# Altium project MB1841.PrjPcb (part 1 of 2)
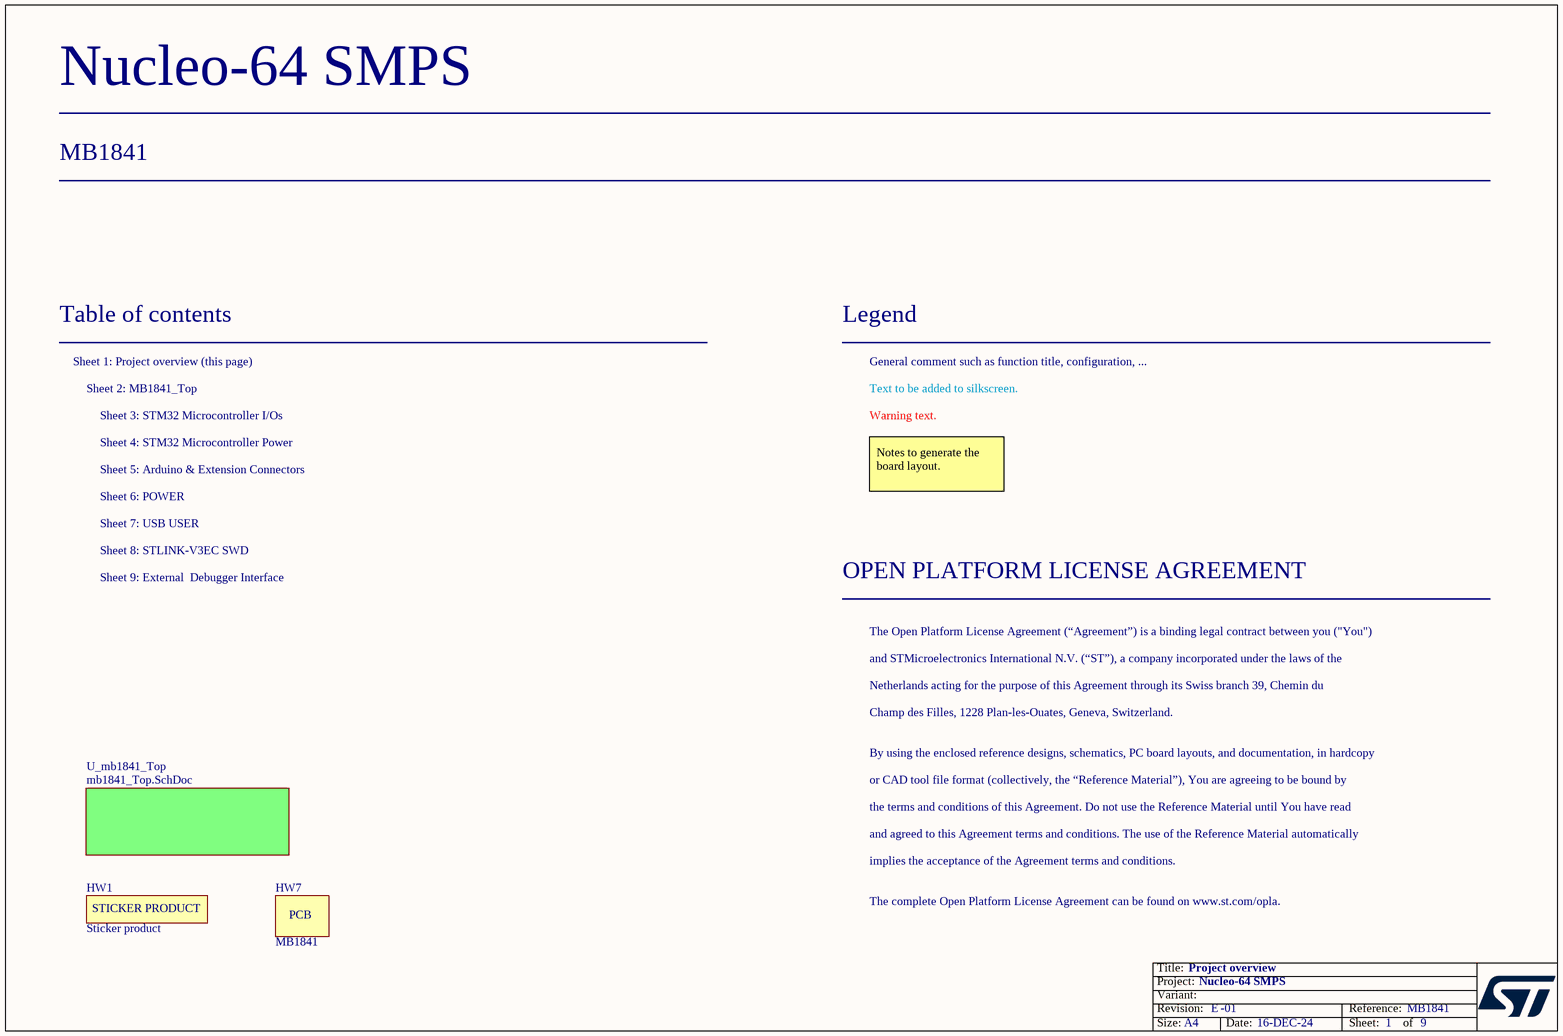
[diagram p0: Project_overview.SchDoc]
Board_Reference: MB1841; Board_PCB_Revision: E; Board_Name: Nucleo-64 SMPS; Board_Document_Date: 16-DEC-24; Board_Assembly_Revision: 01
9 sheets, 261 parts. Net scope: flat (ports and power ports of the same name join across sheets).
Board file: MB1841.PcbDoc
Sheets:
  Project_overview.SchDoc
    U_mb1841_Top = mb1841_Top.SchDoc
      U_Arduino_extension_connectors = Arduino_extension_connectors.SchDoc
      U_Power = Power.SchDoc
      U_STM32_microcontroller_IOs = STM32_microcontroller_IOs.SchDoc
      U_STM32_microcontroller_power = STM32_microcontroller_power.SchDoc
      U_USB = USB.SchDoc
      U_STLink_V3EC = STLink_V3EC.SchDoc
      U_External_Debug_Interface = External_Debug_Interface.SchDoc

## Sheet Project_overview.SchDoc: Project overview
size A4; Date: Not used; ApprovedBy: Not used; CheckedBy: Not used; Author: Not used; CompanyName: STMicroelectronics; DrawnBy: Not used; Engineer: Not used; Organization: Not used; Address1: Not used; Address2: Not used; Address3: Not used; Address4: Not used; DocumentNumber: 1; Revision: Not used; SheetNumber: 1; SheetTotal: 9

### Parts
HW1  value Sticker product  [STICKER_PRODUCT_25X9]  (hidden comment: STICKER_PRODUCT)  (no BOM)
HW7  value MB1841  (hidden comment: PCB)  (no BOM)

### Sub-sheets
U_mb1841_Top = mb1841_Top.SchDoc: no entries

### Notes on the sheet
- Table of contents
- Sheet 1: Project overview (this page)
- Legend
- General comment such as function title, configuration, ...
- Sheet 2: MB1841_Top
- Sheet 4: STM32 Microcontroller Power
- Sheet 3: STM32 Microcontroller I/Os
- Text to be added to silkscreen.
- Warning text.
- Sheet 6: POWER
- Sheet 5: Arduino & Extension Connectors
- Notes to generate the board layout.
- Sheet 8: STLINK-V3EC SWD
- Sheet 7: USB USER
- Sheet 9: External  Debugger Interface
- OPEN PLATFORM LICENSE AGREEMENT
- The Open Platform License Agreement (“Agreement”) is a binding legal contract between you ("You")
- and STMicroelectronics International N.V. (“ST”), a company incorporated under the laws of the
- Netherlands acting for the purpose of this Agreement through its Swiss branch 39, Chemin du
- Champ des Filles, 1228 Plan-les-Ouates, Geneva, Switzerland.
- By using the enclosed reference designs, schematics, PC board layouts, and documentation, in hardcopy
- or CAD tool file format (collectively, the “Reference Material”), You are agreeing to be bound by
- the terms and conditions of this Agreement. Do not use the Reference Material until You have read
- and agreed to this Agreement terms and conditions. The use of the Reference Material automatically
- implies the acceptance of the Agreement terms and conditions.
- The complete Open Platform License Agreement can be found on www.st.com/opla.

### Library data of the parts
HW1 = MCD-00547: Sticker product 25x9 mm; Part_Type: Misc; Part_Preference: Recommended; Component_Country_Of_Origin: Unknown; ShowFields: YES; ID: 3197
HW7 = MCD-04244: MB1841 PCB Nucleo 4L2S; Part_Preference: Recommended; ShowFields: YES; ID: 6360

## Sheet mb1841_Top.SchDoc: Top hierarchical view
size A4; Date: Not used; ApprovedBy: Not used; CheckedBy: Not used; Author: Not used; CompanyName: STMicroelectronics; DrawnBy: Not used; Engineer: Not used; Organization: Not used; Address1: Not used; Address2: Not used; Address3: Not used; Address4: Not used; DocumentNumber: 2; Revision: A-01-P3; SheetNumber: 2; SheetTotal: 9
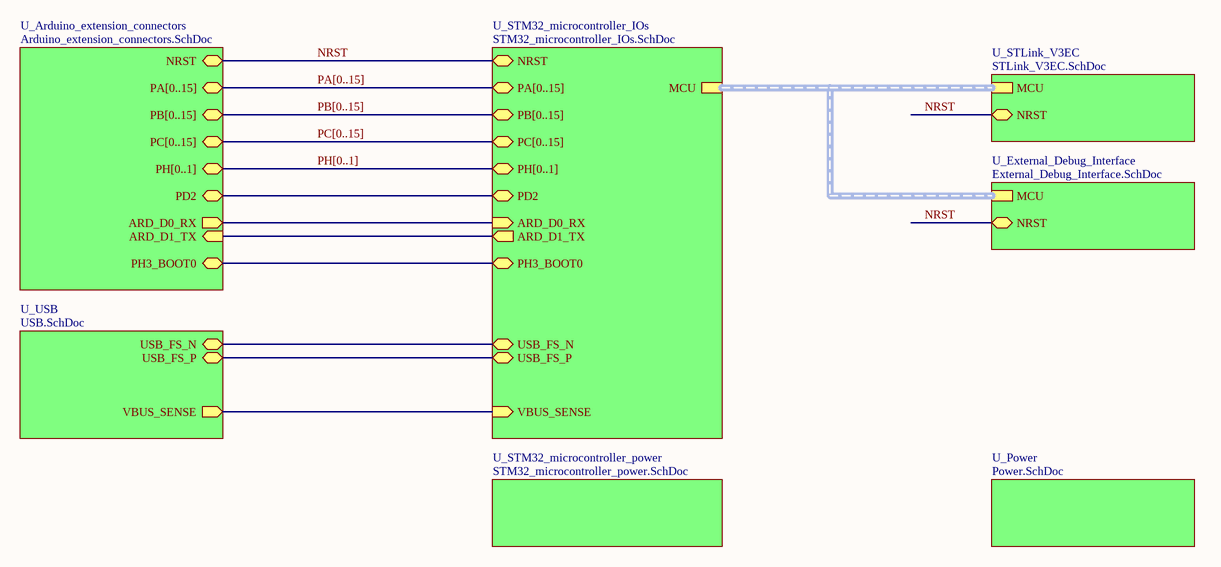
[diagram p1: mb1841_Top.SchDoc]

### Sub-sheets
U_Arduino_extension_connectors = Arduino_extension_connectors.SchDoc: PA[0..15] (bidir), PB[0..15] (bidir), PC[0..15] (bidir), PH[0..1] (bidir), PH3_BOOT0 (bidir), PD2 (bidir), ARD_D0_RX (out), ARD_D1_TX (in), NRST (bidir)
U_External_Debug_Interface = External_Debug_Interface.SchDoc: NRST (bidir), MCU (harness MCU)
U_Power = Power.SchDoc: no entries
U_STLink_V3EC = STLink_V3EC.SchDoc: NRST (bidir), MCU (harness MCU)
U_STM32_microcontroller_IOs = STM32_microcontroller_IOs.SchDoc: PA[0..15] (bidir), PB[0..15] (bidir), PC[0..15] (bidir), PH[0..1] (bidir), PH3_BOOT0 (bidir), ARD_D0_RX (in), PD2 (bidir), ARD_D1_TX (out), USB_FS_P (bidir), USB_FS_N (bidir), VBUS_SENSE (in), MCU (harness MCU), NRST (bidir)
U_STM32_microcontroller_power = STM32_microcontroller_power.SchDoc: no entries
U_USB = USB.SchDoc: USB_FS_N (bidir), USB_FS_P (bidir), VBUS_SENSE (out)

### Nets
NRST: sheet U_Arduino_extension_connectors/NRST, sheet U_STM32_microcontroller_IOs/NRST, sheet U_STLink_V3EC/NRST, sheet U_External_Debug_Interface/NRST
(unnamed): sheet U_Arduino_extension_connectors/PH3_BOOT0, sheet U_STM32_microcontroller_IOs/PH3_BOOT0
(unnamed): sheet U_Arduino_extension_connectors/PD2, sheet U_STM32_microcontroller_IOs/PD2  [a separate net that carries the same name]
(unnamed): sheet U_Arduino_extension_connectors/ARD_D0_RX, sheet U_STM32_microcontroller_IOs/ARD_D0_RX  [a separate net that carries the same name]
(unnamed): sheet U_Arduino_extension_connectors/ARD_D1_TX, sheet U_STM32_microcontroller_IOs/ARD_D1_TX  [a separate net that carries the same name]
(unnamed): sheet U_STM32_microcontroller_IOs/USB_FS_P, sheet U_USB/USB_FS_P  [a separate net that carries the same name]
(unnamed): sheet U_STM32_microcontroller_IOs/USB_FS_N, sheet U_USB/USB_FS_N  [a separate net that carries the same name]
(unnamed): sheet U_STM32_microcontroller_IOs/VBUS_SENSE, sheet U_USB/VBUS_SENSE  [a separate net that carries the same name]

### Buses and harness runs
bus PA[0..15] = sheet U_Arduino_extension_connectors/PA[0..15] = sheet U_STM32_microcontroller_IOs/PA[0..15]
bus PB[0..15] = sheet U_Arduino_extension_connectors/PB[0..15] = sheet U_STM32_microcontroller_IOs/PB[0..15]
bus PC[0..15] = sheet U_Arduino_extension_connectors/PC[0..15] = sheet U_STM32_microcontroller_IOs/PC[0..15]
bus PH[0..1] = sheet U_Arduino_extension_connectors/PH[0..1] = sheet U_STM32_microcontroller_IOs/PH[0..1]
harness sheet U_External_Debug_Interface/MCU = sheet U_STLink_V3EC/MCU = sheet U_STM32_microcontroller_IOs/MCU

## Sheet Arduino_extension_connectors.SchDoc: Arduino & Extension Connectors
size A4; Date: Not used; ApprovedBy: Not used; CheckedBy: Not used; Author: Not used; CompanyName: STMicroelectronics; DrawnBy: Not used; Engineer: Not used; Organization: Not used; Address1: Not used; Address2: Not used; Address3: Not used; Address4: Not used; DocumentNumber: 5; Revision: Not used; SheetNumber: 5; SheetTotal: 9
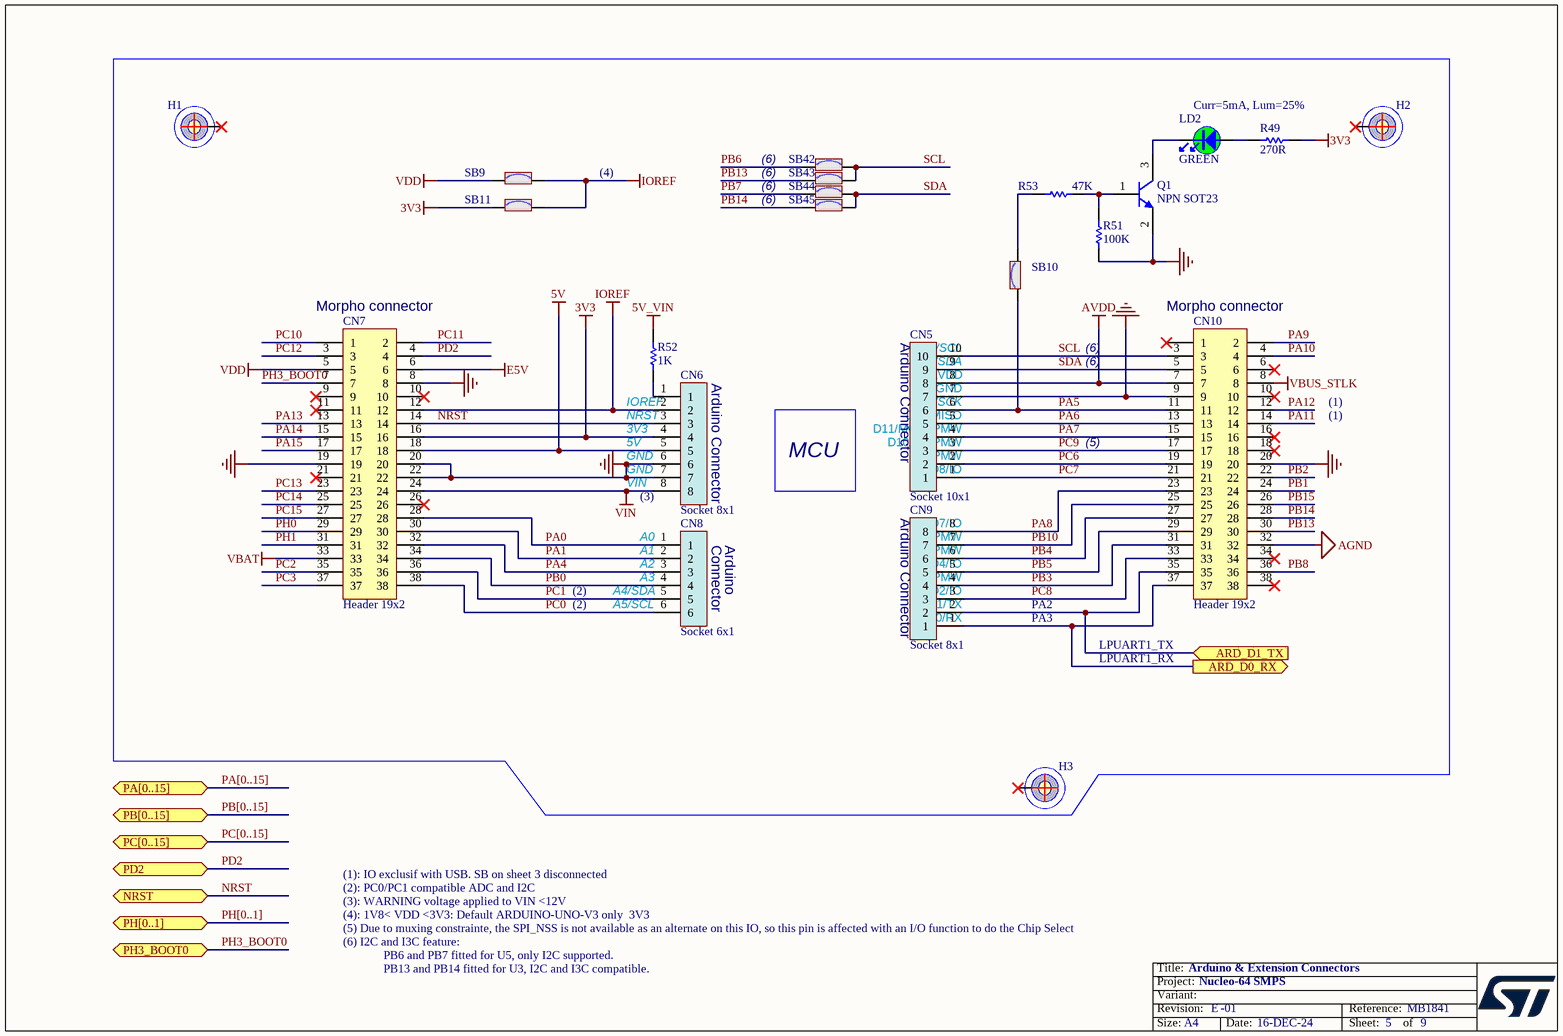
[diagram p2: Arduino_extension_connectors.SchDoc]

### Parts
CN5  Socket 10x1  [CON_SAMTEC_SSQ-110-03-F-S]
CN6  Socket 8x1  [CON_SAMTEC_SSQ-108-03-F-S]
CN7  Header 19x2  [CON_SAMTEC_TSW-119-09-X-D]
CN8  Socket 6x1  [CON_SAMTEC_SSQ-106-03-F-S]
CN9  Socket 8x1  [CON_SAMTEC_SSQ-108-03-F-S]
CN10  Header 19x2  [CON_SAMTEC_TSW-119-09-X-D]
H1  POSITION HOLE  (value not drawn)  (no BOM)
H2  POSITION HOLE  (value not drawn)  (no BOM)
H3  POSITION HOLE  (value not drawn)  (no BOM)
LD2  value GREEN  [LED_0603_OSRAM_LG-Q396-PS-35_GREEN_1A2K_H0P4]  (hidden comment: LED_green)
Q1  value NPN SOT23  [NPN_SOT23]  (hidden comment: 9013-SOT23)
R49  value 270R  [R0402]  (hidden comment: Resistor)
R51  value 100K  [R0402]  (hidden comment: Resistor)
R52  value 1K  [R0402]  (hidden comment: Resistor)
R53  value 47K  [R0402]  (hidden comment: Resistor)
SB9  SB_ON  [SOLDER-BRIDGE_R0603-0R]  (value not drawn)
SB10  SB_ON  [SOLDER-BRIDGE_R0603-0R]  (value not drawn)
SB11  SB_ON  [SOLDER-BRIDGE_R0603-0R]  (value not drawn)
SB42  SB_ON  [SOLDER-BRIDGE_R0603-0R]  (value not drawn)
SB43  SB_ON  [SOLDER-BRIDGE_R0603-0R]  (value not drawn)
SB44  SB_ON  [SOLDER-BRIDGE_R0603-0R]  (value not drawn)
SB45  SB_ON  [SOLDER-BRIDGE_R0603-0R]  (value not drawn)

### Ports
ARD_D0_RX (out), ARD_D1_TX (in), NRST (bidir), PA[0..15] (bidir), PB[0..15] (bidir), PC[0..15] (bidir), PD2 (bidir), PH3_BOOT0 (bidir), PH[0..1] (bidir)

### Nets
3V3: CN6.4 CN7.16 R49.2 SB11.1
5V: CN6.5 CN7.18
5V_VIN: R52.1
AGND: CN10.32
AVDD: CN5.8 CN10.7
E5V: CN7.6
GND: CN5.7 CN6.6 CN6.7 CN7.8 CN7.19 CN7.20 CN7.22 CN10.9 CN10.20 Q1.2(E) R51.1
IOREF: CN6.2 CN7.12 SB9.2 SB11.2
VBAT: CN7.33
VBUS_STLK: CN10.8
VDD: CN7.5 SB9.1
VIN: CN6.8 CN7.24
ARD_D0_RX: CN9.1 CN10.37 ; port ARD_D0_RX
ARD_D1_TX: CN9.2 CN10.35 ; port ARD_D1_TX
NRST: CN6.3 CN7.14 ; port NRST
PA0: CN7.28 CN8.1
PA1: CN7.30 CN8.2
PA4: CN7.32 CN8.3
PA5: CN5.6 CN10.11 SB10.1
PA6: CN5.5 CN10.13
PA7: CN5.4 CN10.15
PA8: CN9.8 CN10.23
PA9: CN10.2
PA10: CN10.4
PA11: CN10.14
PA12: CN10.12
PA13: CN7.13
PA14: CN7.15
PA15: CN7.17
PB0: CN7.34 CN8.4
PB1: CN10.24
PB2: CN10.22
PB3: CN9.4 CN10.31
PB4: CN9.6 CN10.27
PB5: CN9.5 CN10.29
PB6: SB42.1
PB7: SB44.1
PB8: CN10.36
PB10: CN9.7 CN10.25
PB13: CN10.30 SB43.1
PB14: CN10.28 SB45.1
PB15: CN10.26
PC0: CN7.38 CN8.6
PC1: CN7.36 CN8.5
PC2: CN7.35
PC3: CN7.37
PC6: CN5.2 CN10.19
PC7: CN5.1 CN10.21
PC8: CN9.3 CN10.33
PC9: CN5.3 CN10.17
PC10: CN7.1
PC11: CN7.2
PC12: CN7.3
PC13: CN7.23
PC14: CN7.25
PC15: CN7.27
PD2: CN7.4 ; port PD2
PH0: CN7.29
PH1: CN7.31
PH3_BOOT0: CN7.7 ; port PH3_BOOT0
SCL: CN5.10 CN10.3 SB42.2 SB43.2
SDA: CN5.9 CN10.5 SB44.2 SB45.2
NetCN6_1: CN6.1 R52.2
NetLD2_1: LD2.1 R49.1
NetLD2_2: LD2.2 Q1.3(C)
NetQ1_1: Q1.1(B) R51.2 R53.2
NetR53_1: R53.1 SB10.2

Not connected (* = marked no-connect by the designer): CN7 9* 10* 11* 21* 26*; CN10 1* 6* 10* 16* 18* 34* 38*; H1 1*; H2 1*; H3 1*

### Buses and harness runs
bus PA[0..15] = port PA[0..15]
bus PB[0..15] = port PB[0..15]
bus PC[0..15] = port PC[0..15]
bus PH[0..1] = port PH[0..1]

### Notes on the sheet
- Curr=5mA, Lum=25%
- (4)
- (6)
- (near CN7) Morpho connector
- (near CN10) Morpho connector
- (near CN6) Arduino Connector
- (near CN5) Arduino Connector
- (near CN5) D14/SDA
- (near CN5) D15/SCL
- (near CN5) AVDD
- (near CN6) 5V
- 3V3
- NRST
- IOREF
- (near CN5) D10/CS/PMW
- (near CN5) D13/SCK
- (near CN5) D12/MISO
- (near CN5) D11/MOSI/PMW
- (near CN5) GND
- (5)
- (1)
- (near CN6) VIN
- (near CN6) GND
- (near CN6) (3)
- MCU
- (near CN9) Arduino Connector
- (near CN5) D8/IO
- (near CN5) D9/PMW
- (near CN8) A0
- (near CN8) A1
- (near CN8) A2
- (near CN8) A3
- (near CN8) Connector
- (near CN8) Arduino
- (near CN9) D4/IO
- (near CN9) D3/PMW
- (near CN9) D5/PMW
- (near CN9) D6/PMW
- (near CN9) D7/IO
- (2)
- (near CN8) A4/SDA
- (near CN8) A5/SCL
- (near CN9) D0/RX
- (near CN9) D1/TX
- (near CN9) D2/IO
- PA2
- PA3
- LPUART1_TX
- LPUART1_RX
- (2): PC0/PC1 compatible ADC and I2C
- (1): IO exclusif with USB. SB on sheet 3 disconnected
- (4): 1V8< VDD <3V3: Default ARDUINO-UNO-V3 only  3V3
- (3): WARNING voltage applied to VIN <12V
- (5) Due to muxing constrainte, the SPI_NSS is not available as an alternate on this IO, so this pin is affected with an I/O function to do the Chip Select
- (6) I2C and I3C feature:
- PB6 and PB7 fitted for U5, only I2C supported.
- PB13 and PB14 fitted for U3, I2C and I3C compatible.

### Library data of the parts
CN5 = MCD-02625: Socket, 10x1, 2.54mm, VR, TH, T=8.51mm/10mm; Part_Type: Connector; Part_Preference: Recommended; Manufacturer: SAMTEC; Manufacturer_Part_Number: SSQ-110-03-F-S; Order_Code_RS: 154-8308; Component_Country_Of_Origin: China, Costa Rica,  Malaysia, Vietnam, USA; ShowFields: YES; ID: 4731
CN6 CN9 = MCD-02624: Socket, 8x1, 2.54mm, VR, TH, T=8.51mm/10mm; Part_Type: Connector; Part_Preference: Recommended; Manufacturer: SAMTEC; Manufacturer_Part_Number: SSQ-108-03-F-S; Order_Code_RS: 180-0395; Component_Country_Of_Origin: China, Costa Rica,  Malaysia, Vietnam, USA; ShowFields: YES; ID: 4730
CN7 CN10 = MCD-00213: Header, 19x2, 2.54mm, VR, TH, T=5.84mm/10.16mm; Manufacturer_Part_Number: TSW-119-09-G-D; Manufacturer: SAMTEC; Part_Type: Connector; Part_Preference: Recommended; Component_Country_Of_Origin: China, Costa Rica, Malaysia, United States, Vietnam; ShowFields: YES; ID: 2656
CN8 = MCD-02623: Socket, 6x1, 2.54mm, VR, TH, T=8.51mm/10mm; Part_Type: Connector; Part_Preference: Recommended; Manufacturer: SAMTEC; Manufacturer_Part_Number: SSQ-106-03-F-S; Order_Code_RS: 180-0379; Component_Country_Of_Origin: China, Costa Rica,  Malaysia, Vietnam, USA; ShowFields: YES; ID: 4729
H1-H3 = MCD-03341: POSITION HOLE D3R2 COMPLIANT ARDUINO; Part_Type: Misc; Part_Preference: Recommended; Value: PTH 3.2mm; ShowFields: YES; ID: 5457
LD2 = MCD-00588: LED Green, 0603 SMD, Forward Voltage Typ=2V, Max=2.5V; Part_Type: Display; Manufacturer_Part_Number: LG Q396-PS-35; Manufacturer: OSRAM OPTO SEMICONDUCTORS; Part_Preference: Recommended; Full_Alternate_Internal_Part_Number: MCD-02400; Component_Country_Of_Origin: Unknown; ShowFields: YES; ID: 3155
Q1 = MCD-00073: NPN Bipolar Transistor; Part_Type: IC; Manufacturer_Part_Number: BSR14; Manufacturer: ON SEMICONDUCTOR; Part_Preference: Recommended; Component_Country_Of_Origin: Unknown; ShowFields: YES; ID: 2519
R49 = MCD-00441: Resistor, 270R, 0402, +/-1%, 1/16W; Manufacturer_Part_Number: RC0402FR-07270RL; Manufacturer: YAGEO; Part_Preference: Recommended; Component_Country_Of_Origin: China; ShowFields: YES; ID: 2838
R51 = MCD-00059: Resistor, 100K, 0402, +/-1%, 1/16W; Part_Preference: Recommended; Manufacturer: YAGEO; Manufacturer_Part_Number: RC0402FR-07100KL; Component_Country_Of_Origin: China; ShowFields: YES; ID: 2533
R52 = MCD-00061: Resistor, 1K, 0402, +/-1%,1/16W; Part_Preference: Recommended; Manufacturer: YAGEO; Manufacturer_Part_Number: RC0402FR-071KL; Component_Country_Of_Origin: China; ShowFields: YES; ID: 2532
R53 = MCD-00063: Resistor, 47K, 0402, +/-1%, 1/16W; Manufacturer_Part_Number: RC0402FR-0747KL; Manufacturer: YAGEO; Part_Preference: Recommended; Component_Country_Of_Origin: China; ShowFields: YES; ID: 2528
SB9-SB11 SB42-SB45 = MCD-00071: Solder Bridge ON; Part_Type: Misc; Manufacturer_Part_Number: RC0603JR-070RL; Manufacturer: YAGEO; Part_Preference: Recommended; ShowFields: YES; ID: 2521

## Sheet Power.SchDoc: Power
size A4; Date: Not used; ApprovedBy: Not used; CheckedBy: Not used; Author: Not used; CompanyName: STMicroelectronics; DrawnBy: Not used; Engineer: Not used; Organization: Not used; Address1: Not used; Address2: Not used; Address3: Not used; Address4: Not used; DocumentNumber: 6; Revision: Not used; SheetNumber: 6; SheetTotal: 9
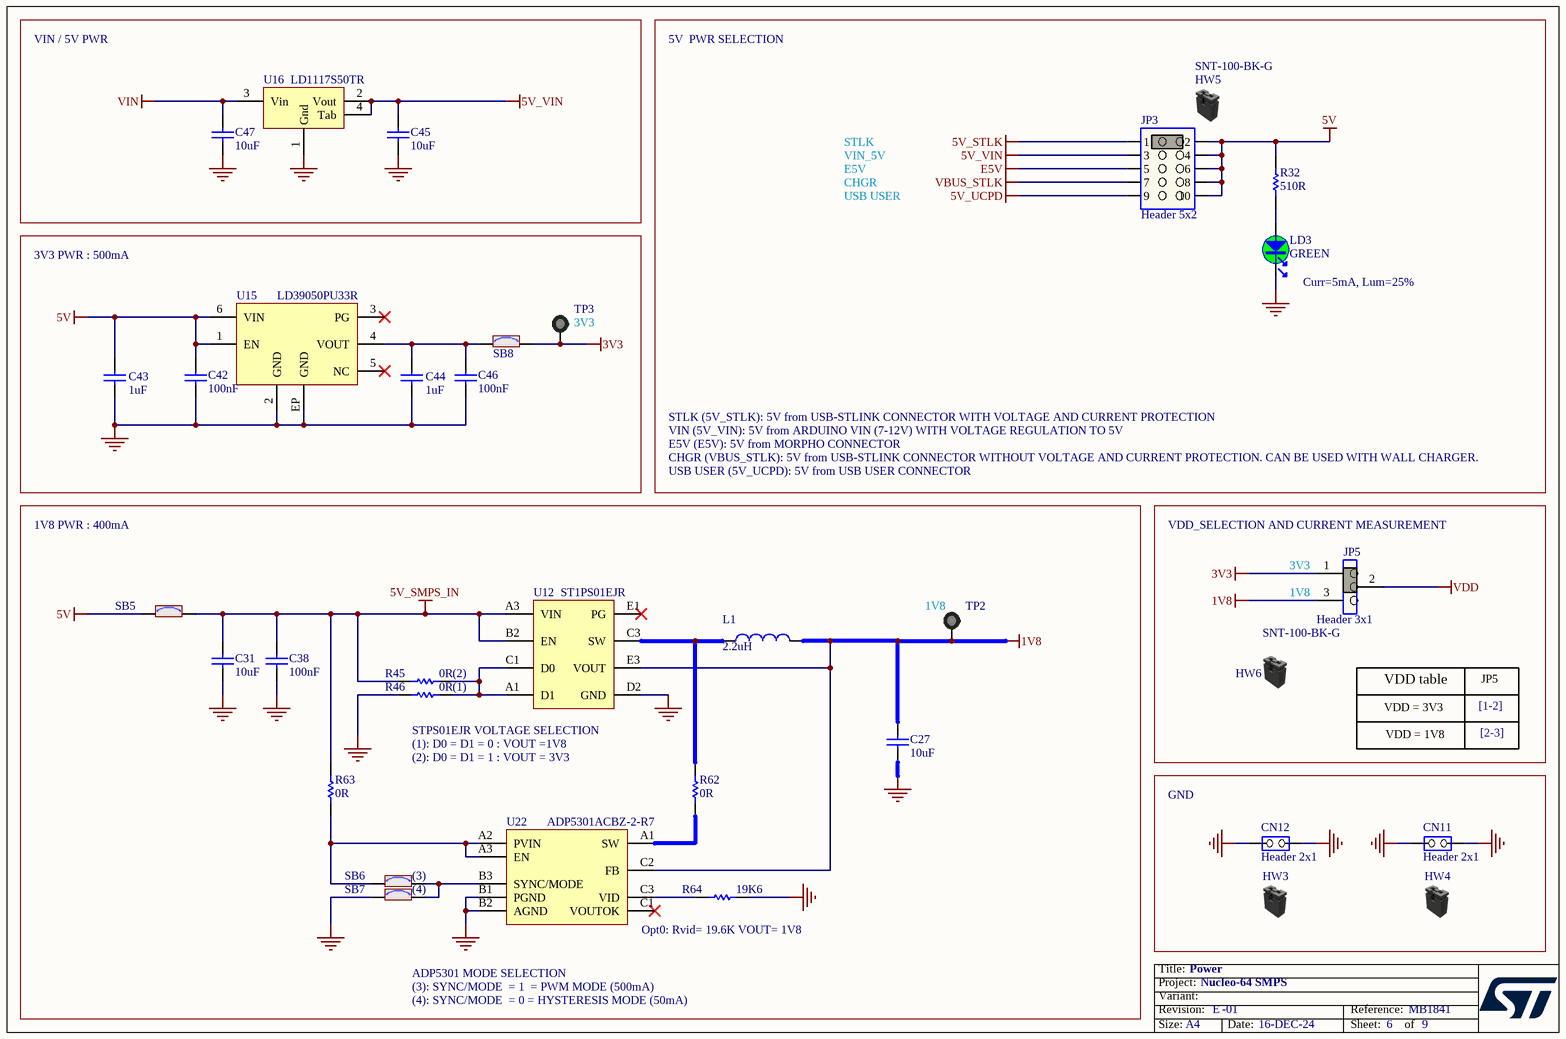
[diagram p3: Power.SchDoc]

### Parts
C27  value 10uF  [C0603]  (hidden comment: Capacitor)
C31  value 10uF  [C0603]  (hidden comment: Capacitor)
C38  value 100nF  [C0402]  (hidden comment: Capacitor)
C42  value 100nF  [C0402]  (hidden comment: Capacitor)
C43  value 1uF  [C0603]  (hidden comment: Capacitor)
C44  value 1uF  [C0603]  (hidden comment: Capacitor)
C45  value 10uF  [C0805]  (hidden comment: Capacitor)
C46  value 100nF  [C0402]  (hidden comment: Capacitor)
C47  value 10uF  [C0805]  (hidden comment: Capacitor)
CN11  value Header 2x1  [CON_SAMTEC_TSW-102-09-X-S]  (hidden comment: Jumper_Header 2x1)
CN12  value Header 2x1  [CON_SAMTEC_TSW-102-09-X-S]  (hidden comment: Jumper_Header 2x1)
HW3  Shunt Black 2.54mm  (value not drawn)  (mechanical)
HW4  Shunt Black 2.54mm  (value not drawn)  (mechanical)
HW5  value SNT-100-BK-G  (hidden comment: Shunt Black 2.54mm)  (mechanical)
HW6  value SNT-100-BK-G  (hidden comment: Shunt Black 2.54mm)  (mechanical)
JP3  value Header 5x2  [CON_SAMTEC_TSW-105-07-X-D]  (hidden comment: Jumper_Header 5x2 Fitted 1-2)
JP5  value Header 3x1  [CON_SAMTEC_TSW-103-07-F-S]  (hidden comment: Jumper_Header 3x1 Fitted 1-2)
L1  value 2.2uH  [IND_TDK_VLS252010HBX-1]  (hidden comment: Inductor)
LD3  value GREEN  [LED_0603_OSRAM_LG-Q396-PS-35_GREEN_1A2K_H0P4]  (hidden comment: LED_green)
R32  value 510R  [R0603]  (hidden comment: Resistor)
R45  value 0R  [R0603]  (hidden comment: Resistor)
R46  value 0R  [R0603]  (hidden comment: Resistor)
R62  value 0R  [R0603]  (hidden comment: Resistor)
R63  value 0R  [R0603]  (hidden comment: Resistor)
R64  value 19K6  [R0603]  (hidden comment: Resistor)
SB5  SB_ON  [SOLDER-BRIDGE_R0603-0R]  (value not drawn)
SB6  SB_ON  [SOLDER-BRIDGE_R0603-0R]  (value not drawn)
SB7  SB_ON  [SOLDER-BRIDGE_R0603-0R]  (value not drawn)
SB8  SB_ON  [SOLDER-BRIDGE_R0603-0R]  (value not drawn)
TP2  Test_Point_PTH_1mm_2mm  [TP_PTH_1MM_2MM]  (value not drawn)  (no BOM)
TP3  Test_Point_PTH_1mm_2mm  [TP_PTH_1MM_2MM]  (value not drawn)  (no BOM)
U12  ST1PS01EJR  [ICC_FLIP-CHIP-BGA8_1P11X1P41_P040]
U15  LD39050PU33R  [ICC_DFN6-EPAD_3X3_P095]
U16  LD1117S50TR  [REG_SOT223-TAB]
U22  value ADP5301ACBZ-2-R7  [ICC_WLCSP9_1P65X1P87_P050]  (hidden comment: ADP5301)

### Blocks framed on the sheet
VIN / 5V PWR: C45 C47 U16
VDD table: HW6 JP5
GND: CN11 CN12 HW3 HW4

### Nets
1V8: C27.2 JP5.3 L1.2 TP2.1 U12.E3(VOUT) U22.C2(FB)
3V3: JP5.1 SB8.2 TP3.1
5V: C42.2 C43.2 JP3.2 JP3.4 JP3.6 JP3.8 JP3.10 R32.2 SB5.1 U15.1(EN) U15.6(VIN)
5V_SMPS_IN: C31.2 C38.2 R45.2 R63.1 SB5.2 U12.A3(VIN) U12.B2(EN)
5V_STLK: JP3.1
5V_UCPD: JP3.9
5V_VIN: C45.2 JP3.3 U16.2(Vout) U16.4(Tab)
E5V: JP3.5
GND: C27.1 C31.1 C38.1 C42.1 C43.1 C44.1 C45.1 C46.1 C47.1 CN11.1(COMMON) CN11.2(NO) CN12.1(COMMON) CN12.2(NO) LD3.2 R46.2 R64.2 SB7.1 U12.D2(GND) U15.2(GND) U15.EP(GND) U16.1(Gnd) U22.B1(PGND) U22.B2(AGND)
VBUS_STLK: JP3.7
VDD: JP5.2
VIN: C47.2 U16.3(Vin)
NetC44_2: C44.2 C46.2 SB8.1 U15.4(VOUT)
NetL1_1: L1.1 R62.1 U12.C3(SW)
NetLD3_1: LD3.1 R32.1
NetR45_1: R45.1 R46.1 U12.A1(D1) U12.C1(D0)
NetR62_2: R62.2 U22.A1(SW)
NetR63_2: R63.2 SB6.1 U22.A2(PVIN) U22.A3(EN)
NetR64_1: R64.1 U22.C3(VID)
NetSB6_2: SB6.2 SB7.2 U22.B3(SYNC/MODE)

Not connected (* = marked no-connect by the designer): U12 E1(PG)*; U15 3(PG)* 5(NC)*; U22 C1(VOUTOK)*

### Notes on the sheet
- 5V  PWR SELECTION
- STLK
- E5V
- VIN_5V
- CHGR
- USB USER
- 3V3 PWR : 500mA
- (near LD3) Curr=5mA, Lum=25%
- (near TP3) 3V3
- STLK (5V_STLK): 5V from USB-STLINK CONNECTOR WITH VOLTAGE AND CURRENT PROTECTION
- VIN (5V_VIN): 5V from ARDUINO VIN (7-12V) WITH VOLTAGE REGULATION TO 5V
- E5V (E5V): 5V from MORPHO CONNECTOR
- CHGR (VBUS_STLK): 5V from USB-STLINK CONNECTOR WITHOUT VOLTAGE AND CURRENT PROTECTION. CAN BE USED WITH WALL CHARGER.
- USB USER (5V_UCPD): 5V from USB USER CONNECTOR
- 1V8 PWR : 400mA
- (near JP5) VDD_SELECTION AND CURRENT MEASUREMENT
- (near JP5) 3V3
- (near TP2) 1V8
- (near JP5) 1V8
- (1)
- (2)
- VDD = 3V3
- [1-2]
- JP5
- STPS01EJR VOLTAGE SELECTION
  (1): D0 = D1 = 0 : VOUT =1V8
  (2): D0 = D1 = 1 : VOUT = 3V3
- VDD = 1V8
- [2-3]
- (near SB6) (3)
- (4)
- Opt0: Rvid= 19.6K VOUT= 1V8
- ADP5301 MODE SELECTION
  (3): SYNC/MODE  = 1  = PWM MODE (500mA)
  (4): SYNC/MODE  = 0 = HYSTERESIS MODE (50mA)

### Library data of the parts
C27 C31 = MCD-00243: Capacitor, MLCC, 10uF, 6V3, X5R, +/-10%, 0603, T=0.8mm; Manufacturer_Part_Number: CC0603KRX5R5BB106; Manufacturer: YAGEO; Part_Preference: Recommended; Component_Country_Of_Origin: China; ShowFields: YES; ID: 2626
C38 = MCD-00006: Capacitor, MLCC, 100nF, 16V, X7R, +/-10%, 0402, T=0.5mm; Manufacturer_Part_Number: CC0402KRX7R7BB104; Manufacturer: YAGEO; Part_Preference: Recommended; Order_Code_RS: 616-9701; Component_Country_Of_Origin: China; ShowFields: YES; ID: 2474
C42 C46 = MCD-00006: Capacitor, MLCC, 100nF, 16V, X7R, +/-10%, 0402, T=0.5mm; Part_Preference: Recommended; Manufacturer: YAGEO; Manufacturer_Part_Number: CC0402KRX7R7BB104; Order_Code_RS: 616-9701; Component_Country_Of_Origin: China; ShowFields: YES; ID: 2474
C43 C44 = MCD-00010: Capacitor, MLCC, 1uF, 16V, X5R, +/-10%, 0603, T=0.8mm; Manufacturer_Part_Number: CC0603KRX5R7BB105; Manufacturer: YAGEO; Part_Preference: Recommended; Component_Country_Of_Origin: China; ShowFields: YES; ID: 2470
C45 C47 = MCD-00014: Capacitor, MLCC, 10uF, 25V, X5R, +/-10%, 0805, T=0.85mm; Manufacturer_Part_Number: CC0805KRX5R8BB106; Manufacturer: YAGEO; Part_Preference: Recommended; Full_Alternate_Internal_Part_Number: MCD-02385; Partial_Alternate_Internal_Part_Number: MCD-03053; Component_Country_Of_Origin: China; ShowFields: YES; ID: 2468
CN11 CN12 = MCD-00214: Header, 2x1, 2.54mm, VR, TH, T=5.84mm/10.16mm; Part_Type: Connector; Part_Preference: Recommended; Manufacturer: SAMTEC; Manufacturer_Part_Number: TSW-102-09-G-S; Full_Alternate_Internal_Part_Number: MCD-02393; Order_Code_RS: 180-3129; Component_Country_Of_Origin: China, Costa Rica, Malaysia, United States, Vietnam; ShowFields: YES; ID: 2652
HW3 HW4 = MCD-00043: SHUNT 2.54mm BLACK; Part_Type: Misc; Part_Preference: Recommended; Manufacturer: SAMTEC; Full_Alternate_Internal_Part_Number: MCD-02388; Value: SNT-100-BK-G; Component_Country_Of_Origin: China, Costa Rica, Malaysia, United States, Vietnam; ShowFields: YES; ID: 2551
HW5 HW6 = MCD-00043: SHUNT 2.54mm BLACK; Manufacturer: SAMTEC; Part_Type: Misc; Part_Preference: Recommended; Full_Alternate_Internal_Part_Number: MCD-02388; Component_Country_Of_Origin: China, Costa Rica, Malaysia, United States, Vietnam; ShowFields: YES; ID: 2551
JP3 = MCD-01203: Header, 5x2, 2.54mm, VR, TH, T=5.84mm/2.54mm; Part_Type: Connector; Manufacturer_Part_Number: TSW-105-07-G-D; Manufacturer: SAMTEC; BMS_Part_Number: 9083523; Part_Preference: Recommended; Full_Alternate_Internal_Part_Number: MCD-02391; Order_Code_RS: 161-2267; Component_Country_Of_Origin: China, Costa Rica, Malaysia, United States, Vietnam; ShowFields: YES; ID: 3293
JP5 = MCD-00684: Header, 3x1, 2.54mm, VR, TH, T=5.84mm/2.54mm; Part_Type: Connector; Manufacturer_Part_Number: TSW-103-07-F-S; Manufacturer: SAMTEC; Part_Preference: Recommended; Order_Code_RS: 161-2248; Component_Country_Of_Origin: China, Costa Rica, Malaysia, United States, Vietnam; ShowFields: YES; ID: 3059
L1 = MCD-00240: Inductor, 2.2uH, +/-20%, 2.6A, 100mR, 2.5x2mm, T=1mm; Manufacturer_Part_Number: VLS252010HBX-2R2M-1; Manufacturer: TDK; Part_Preference: Recommended; Order_Code_RS: 181-5270; Component_Country_Of_Origin: Unknown; ShowFields: YES; ID: 2627
LD3 = MCD-00588: as LD2 on sheet Arduino_extension_connectors
R32 = MCD-00225: Resistor, 510R, 0603, +/-1%, 1/10W; Manufacturer_Part_Number: RC0603FR-07510RL; Manufacturer: YAGEO; Part_Preference: Recommended; Component_Country_Of_Origin: China; ShowFields: YES; ID: 2644
R45 R46 R62 R63 = MCD-00056: Resistor, 0R, 0603, +/-5%, 1/10W; Manufacturer_Part_Number: RC0603JR-070RL; Manufacturer: YAGEO; Part_Preference: Recommended; Component_Country_Of_Origin: China; ShowFields: YES; ID: 2536
R64 = MCD-00242: Resistor, 19K6, 0603, +/-1%, 1/10W; Manufacturer_Part_Number: RC0603FR-0719K6L; Manufacturer: YAGEO; Part_Preference: Recommended; Component_Country_Of_Origin: China; ShowFields: YES; ID: 2630
SB5-SB7 = MCD-00071: Solder Bridge ON; Part_Type: Misc; Part_Preference: Recommended; Manufacturer: YAGEO; Manufacturer_Part_Number: RC0603JR-070RL; ShowFields: YES; ID: 2521
SB8 = MCD-00071: as SB9 on sheet Arduino_extension_connectors
TP2 TP3 = MCD-01506: Test Point trought hole 1mm/2mm; Part_Type: Misc; Part_Preference: Recommended; Value: TP; ShowFields: YES; ID: 3606
U12 = MCD-00228: 400mA Nano-Quiescent Step down converter; Manufacturer: STMICROELECTRONICS; Part_Type: IC; BMS_Part_Number: 9176329; Part_Preference: Recommended; Manufacturer_HQ_COO: EU; Component_Country_Of_Origin: Italy; ShowFields: YES; ID: 2642
U15 = MCD-00215: Low quiescent current and low noise voltage regulators; Manufacturer: STMICROELECTRONICS; Part_Type: IC; BMS_Part_Number: 9176126; Part_Preference: Recommended; Manufacturer_HQ_COO: EU; Component_Country_Of_Origin: Malaysia; ShowFields: YES; ID: 2654
U16 = MCD-00088: IC REG LDO 5V 0.8A SOT223; Manufacturer: STMICROELECTRONICS; BMS_Part_Number: 9176133; Part_Preference: Recommended; Manufacturer_HQ_COO: EU; Component_Country_Of_Origin: China; ShowFields: YES; ID: 2503
U22 = MCD-00226: UL Step down regulator: Opt0; Manufacturer: ANALOG DEVICES; Part_Type: IC; Part_Preference: Recommended; Component_Country_Of_Origin: Singapore; ShowFields: YES; ID: 2641

## Sheet STM32_microcontroller_IOs.SchDoc: STM32 microcontroller I/Os
size A4; Date: Not used; ApprovedBy: Not used; CheckedBy: Not used; Author: Not used; CompanyName: STMicroelectronics; DrawnBy: Not used; Engineer: Not used; Organization: Not used; Address1: Not used; Address2: Not used; Address3: Not used; Address4: Not used; DocumentNumber: 3; Revision: Not used; SheetNumber: 3; SheetTotal: 9
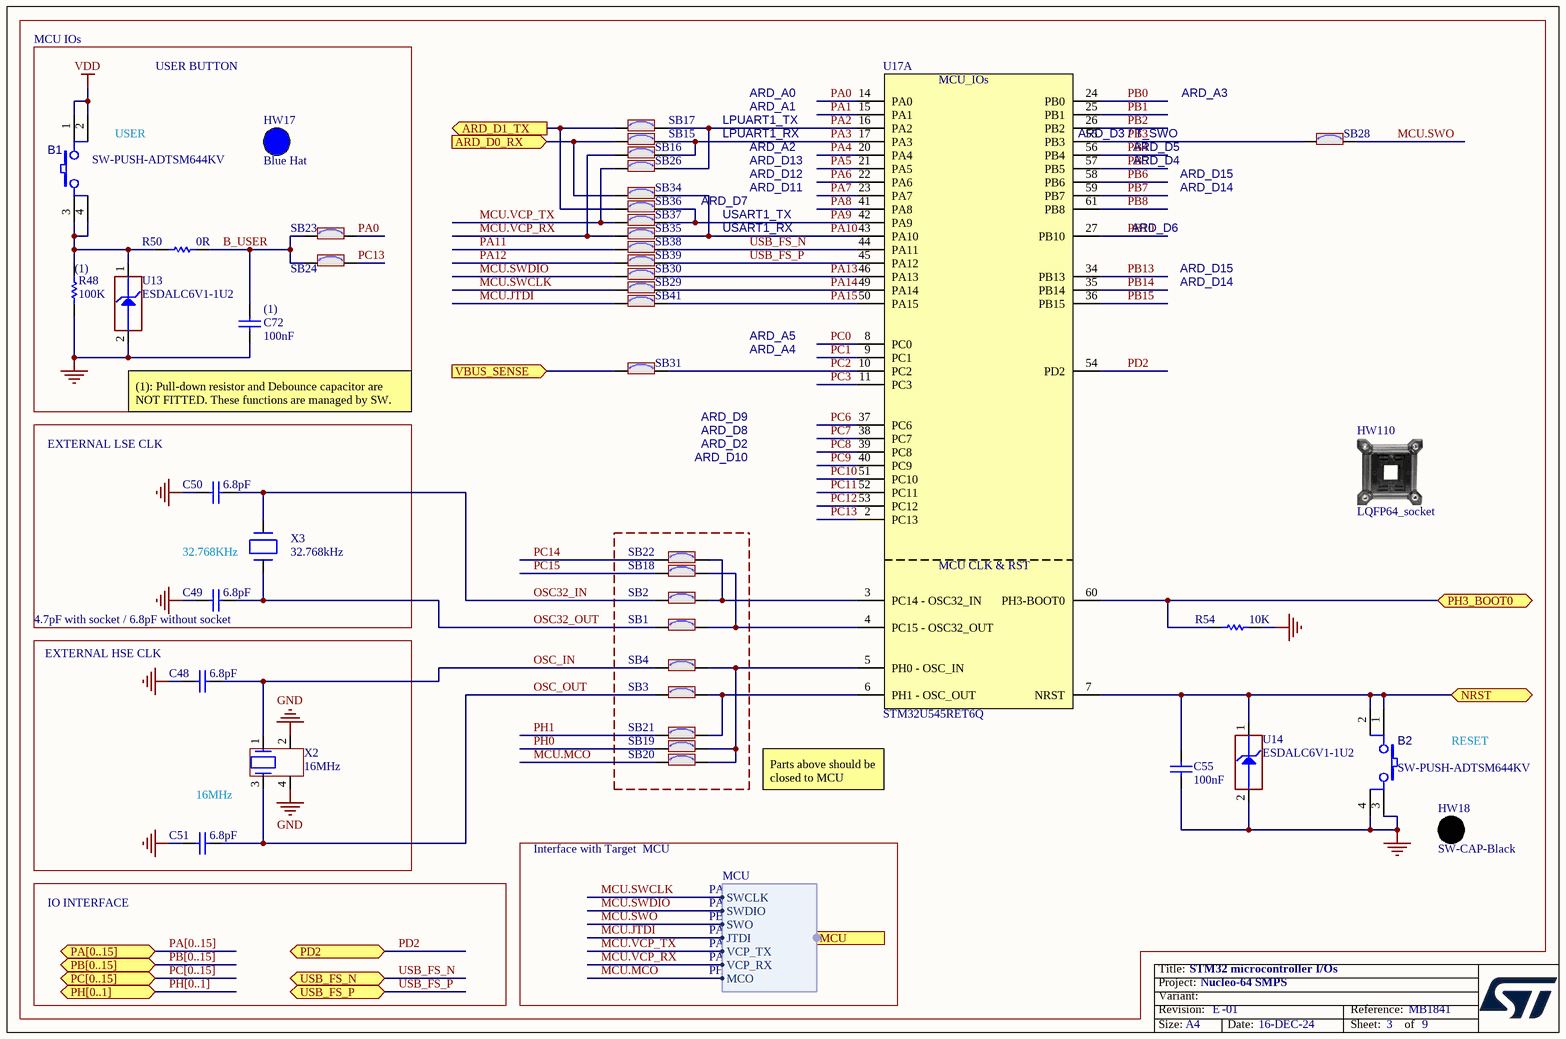
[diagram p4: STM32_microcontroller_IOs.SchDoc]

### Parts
B1  value SW-PUSH-ADTSM644KV  [SWI_APEM_ADTSM644SV_BLUE]  (hidden comment: SW_PUSH_SMD)
B2  value SW-PUSH-ADTSM644KV  [SWI_APEM_ADTSM644KV_BLACK]  (hidden comment: SW_PUSH_SMD)
C48  value 6.8pF  [C0402]  (hidden comment: Capacitor)
C49  value 6.8pF  [C0402]  (hidden comment: Capacitor)
C50  value 6.8pF  [C0402]  (hidden comment: Capacitor)
C51  value 6.8pF  [C0402]  (hidden comment: Capacitor)
C55  value 100nF  [C0402]  (hidden comment: Capacitor)
C72  value 100nF  [C0402]  (hidden comment: Capacitor)
HW17  value Blue Hat  (hidden comment: BUTTON_HAT_BLUE)  (mechanical)
HW18  SW-CAP-Black  [N/A]  (mechanical)
HW110  value LQFP64_socket  (hidden comment: SOCKET_LQFP64)  (mechanical)
R48  value 100K  [R0402]  (hidden comment: Resistor)
R50  value 0R  [R0603]  (hidden comment: Resistor)
R54  value 10K  [R0402]  (hidden comment: Resistor)
SB1  SB_ON  [SOLDER-BRIDGE_R0603-0R]  (value not drawn)
SB2  SB_ON  [SOLDER-BRIDGE_R0603-0R]  (value not drawn)
SB3  SB_ON  [SOLDER-BRIDGE_R0603-0R]  (value not drawn)
SB4  SB_ON  [SOLDER-BRIDGE_R0603-0R]  (value not drawn)
SB15  SB_ON  [SOLDER-BRIDGE_R0603-0R]  (value not drawn)
SB16  SB_ON  [SOLDER-BRIDGE_R0603-0R]  (value not drawn)
SB17  SB_ON  [SOLDER-BRIDGE_R0603-0R]  (value not drawn)
SB18  SB_ON  [SOLDER-BRIDGE_R0603-0R]  (value not drawn)
SB19  SB_ON  [SOLDER-BRIDGE_R0603-0R]  (value not drawn)
SB20  SB_ON  [SOLDER-BRIDGE_R0603-0R]  (value not drawn)
SB21  SB_ON  [SOLDER-BRIDGE_R0603-0R]  (value not drawn)
SB22  SB_ON  [SOLDER-BRIDGE_R0603-0R]  (value not drawn)
SB23  SB_ON  [SOLDER-BRIDGE_R0603-0R]  (value not drawn)
SB24  SB_ON  [SOLDER-BRIDGE_R0603-0R]  (value not drawn)
SB26  SB_ON  [SOLDER-BRIDGE_R0603-0R]  (value not drawn)
SB28  SB_ON  [SOLDER-BRIDGE_R0603-0R]  (value not drawn)
SB29  SB_ON  [SOLDER-BRIDGE_R0603-0R]  (value not drawn)
SB30  SB_ON  [SOLDER-BRIDGE_R0603-0R]  (value not drawn)
SB31  SB_ON  [SOLDER-BRIDGE_R0603-0R]  (value not drawn)
SB34  SB_ON  [SOLDER-BRIDGE_R0603-0R]  (value not drawn)
SB35  SB_ON  [SOLDER-BRIDGE_R0603-0R]  (value not drawn)
SB36  SB_ON  [SOLDER-BRIDGE_R0603-0R]  (value not drawn)
SB37  SB_ON  [SOLDER-BRIDGE_R0603-0R]  (value not drawn)
SB38  SB_ON  [SOLDER-BRIDGE_R0603-0R]  (value not drawn)
SB39  SB_ON  [SOLDER-BRIDGE_R0603-0R]  (value not drawn)
SB41  SB_ON  [SOLDER-BRIDGE_R0603-0R]  (value not drawn)
U13  value ESDALC6V1-1U2  [ESD_ST0201]  (hidden comment: ESD-TRANSIL)
U14  value ESDALC6V1-1U2  [ESD_ST0201]  (hidden comment: ESD-TRANSIL)
U17  STM32U545RET6Q  [ICC_LQFP64_10X10_P050_SOCKET_YAMAICHI_IC149-064-069-B5_NM]  (part A of 2)
X2  value 16MHz  [CRY_NX2016SA_4P]  (hidden comment: XTAL_4_PINS)
X3  value 32.768kHz  [CRY_NX1610SE_2P]  (hidden comment: XTAL_2_PINS)

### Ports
ARD_D0_RX (in), ARD_D1_TX (out), MCU (harness MCU), NRST (bidir), PA[0..15] (bidir), PB[0..15] (bidir), PC[0..15] (bidir), PD2 (bidir), PH3_BOOT0 (bidir), PH[0..1] (bidir), USB_FS_N (bidir), USB_FS_P (bidir), VBUS_SENSE (in)

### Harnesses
MCU: SWCLK, SWDIO, SWO, JTDI, VCP_RX, VCP_TX, MCO

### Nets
GND: B2.3 B2.4 C48.1 C49.1 C50.1 C51.1 C55.1 C72.1 R48.1 R54.1 U13.2(GND) U14.2(GND) X2.2 X2.4
VDD: B1.1 B1.2
ARD_D0_RX: SB15.2 SB34.1 ; port ARD_D0_RX
ARD_D1_TX: SB17.2 SB36.1 ; port ARD_D1_TX
B_USER: C72.2 R50.2 SB23.1 SB24.1
MCU.JTDI: SB41.1 ; port MCU.JTDI
MCU.MCO: SB20.1 ; port MCU.MCO
MCU.SWCLK: SB29.1 ; port MCU.SWCLK
MCU.SWDIO: SB30.1 ; port MCU.SWDIO
MCU.SWO: SB28.2 ; port MCU.SWO
MCU.VCP_RX: SB16.1 SB35.1 ; port MCU.VCP_RX
MCU.VCP_TX: SB26.1 SB37.1 ; port MCU.VCP_TX
NRST: B2.1 B2.2 C55.2 U14.1(IO1) U17.7(NRST) ; port NRST
OSC32_IN: C50.2 SB2.1 X3.2(X2)
OSC32_OUT: C49.2 SB1.1 X3.1(X1)
OSC_IN: C48.2 SB4.1 X2.1
OSC_OUT: C51.2 SB3.1 X2.3
PA0: SB23.2 U17.14(PA0)
PA1: U17.15(PA1)
PA2: SB17.1 SB26.2 U17.16(PA2)
PA3: SB15.1 SB16.2 U17.17(PA3)
PA4: U17.20(PA4)
PA5: U17.21(PA5)
PA6: U17.22(PA6)
PA7: U17.23(PA7)
PA8: U17.41(PA8)
PA9: SB36.2 SB37.2 U17.42(PA9)
PA10: SB34.2 SB35.2 U17.43(PA10)
PA11: SB38.1
PA12: SB39.1
PA13: SB30.2 U17.46(PA13)
PA14: SB29.2 U17.49(PA14)
PA15: SB41.2 U17.50(PA15)
PB0: U17.24(PB0)
PB1: U17.25(PB1)
PB2: U17.26(PB2)
PB3: SB28.1 U17.55(PB3)
PB4: U17.56(PB4)
PB5: U17.57(PB5)
PB6: U17.58(PB6)
PB7: U17.59(PB7)
PB8: U17.61(PB8)
PB10: U17.27(PB10)
PB13: U17.34(PB13)
PB14: U17.35(PB14)
PB15: U17.36(PB15)
PC0: U17.8(PC0)
PC1: U17.9(PC1)
PC2: SB31.2 U17.10(PC2)
PC3: U17.11(PC3)
PC6: U17.37(PC6)
PC7: U17.38(PC7)
PC8: U17.39(PC8)
PC9: U17.40(PC9)
PC10: U17.51(PC10)
PC11: U17.52(PC11)
PC12: U17.53(PC12)
PC13: SB24.2 U17.2(PC13)
PC14: SB22.1
PC15: SB18.1
PD2: U17.54(PD2) ; port PD2
PH0: SB19.1
PH1: SB21.1
PH3_BOOT0: R54.2 U17.60(PH3-BOOT0) ; port PH3_BOOT0
USB_FS_N: SB38.2 U17.44(PA11) ; port USB_FS_N
USB_FS_P: SB39.2 U17.45(PA12) ; port USB_FS_P
VBUS_SENSE: SB31.1 ; port VBUS_SENSE
NetB1_3: B1.3 B1.4 R48.2 R50.1 U13.1(IO1)
NetSB1_2: SB1.2 SB18.2 U17.4(PC15_-_OSC32_OUT)
NetSB2_2: SB2.2 SB22.2 U17.3(PC14_-_OSC32_IN)
NetSB3_2: SB3.2 SB21.2 U17.6(PH1_-_OSC_OUT)
NetSB4_2: SB4.2 SB19.2 SB20.2 U17.5(PH0_-_OSC_IN)

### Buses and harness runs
bus PA[0..15] = port PA[0..15]
bus PB[0..15] = port PB[0..15]
bus PC[0..15] = port PC[0..15]
bus PH[0..1] = port PH[0..1]

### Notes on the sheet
- MCU IOs
- USER BUTTON
- ARD_A0
- ARD_A1
- ARD_A3
- (near B1) USER
- LPUART1_TX
- LPUART1_RX
- ARD_A2
- ARD_D12
- ARD_D13
- ARD_D15
- (near SB28) ARD_D3 / T_SWO
- ARD_D4
- ARD_D5
- USART1_TX
- USART1_RX
- ARD_D11
- ARD_D7
- ARD_D6
- ARD_D14
- (near R48) (1)
- (near C72) (1)
- ARD_A4
- ARD_A5
- EXTERNAL LSE CLK
- (1): Pull-down resistor and Debounce capacitor are NOT FITTED. These functions are managed by SW.
- ARD_D8
- ARD_D2
- ARD_D9
- ARD_D10
- 32.768KHz
- (near C49) 4.7pF with socket / 6.8pF without socket
- EXTERNAL HSE CLK
- Parts above should be closed to MCU
- RESET
- 16MHz
- Interface with Target  MCU
- IO INTERFACE
- PA14
- PA13
- PB3
- PA15
- PA10
- PA9
- PH0

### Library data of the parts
B1 B2 = MCD-02524: Push Button, SPST-NO, 0.05A, 12V SMT, T=7.30mm, changeable caps AKTSC62x; Part_Type: Misc; Part_Preference: Recommended; Manufacturer: APEM INC; Manufacturer_Part_Number: ADTSM644SVTR; ShowFields: YES; ID: 4630
C48-C51 = MCD-00674: Capacitor, MLCC, 6.8pF, 50V, NPO, +/-0.25pF, 0402, T=0.5mm; Manufacturer_Part_Number: CC0402CRNPO9BN6R8; Manufacturer: YAGEO; Part_Preference: Recommended; Component_Country_Of_Origin: China; ShowFields: YES; ID: 3068
C55 C72 = MCD-00006: as C42 on sheet Power
HW17 = MCD-02136: Switch hat, blue, For KTSC-62B; Part_Type: Misc; Part_Preference: Recommended; Manufacturer: APEM INC; Manufacturer_Part_Number: AKTSC62B; Order_Code_RS: 378-6779; Component_Country_Of_Origin: Unknown; ShowFields: YES; ID: 4236
HW18 = MCD-02526: Black round cap for ADTSM644KV; Part_Type: Mechanical; Part_Preference: Recommended; Manufacturer: APEM INC; Manufacturer_Part_Number: AKTSC62K; Value: SW-CAP-AKTSC62K; ShowFields: YES; ID: 4632
HW110 = MCD-01253: Socket_IC, LQFP64, pitch 0.5mm, with positioning pins; Manufacturer_Part_Number: IC149-064-169-B5; Manufacturer: YAMAICHI; Part_Preference: Recommended; Component_Country_Of_Origin: Unknown; ShowFields: YES; ID: 3244
R48 = MCD-00059: as R51 on sheet Arduino_extension_connectors
R50 = MCD-00056: as R45 on sheet Power
R54 = MCD-00053: Resistor, 10K, 0402, +/-1%, 1/16W; Manufacturer_Part_Number: RC0402FR-0710KL; Manufacturer: YAGEO; BMS_Part_Number: 9131590; Part_Preference: Recommended; Component_Country_Of_Origin: China; ShowFields: YES; ID: 2539
SB1-SB4 SB15-SB24 SB26 SB28-SB31 SB34-SB39 SB41 = MCD-00071: as SB9 on sheet Arduino_extension_connectors
U13 U14 = MCD-00170: ESD protection 6V1; Part_Type: Diode; Manufacturer: STMICROELECTRONICS; BMS_Part_Number: 9151132; Part_Preference: Recommended; Manufacturer_HQ_COO: EU; Component_Country_Of_Origin: China; ShowFields: YES; ID: 2696
U17 = MCD-03267: MCU, Arm Cortex®-M33 32-bit MCU, 512 KB Flash memory, 274 KB SRAM, SMPS, Ultra-low-power, CRYPTO; Part_Type: IC; Part_Preference: Recommended; Manufacturer: STMICROELECTRONICS; ShowFields: YES; ID: 5383
X2 = MCD-01476: Crystal, 16 MHz, 8pF, +/-20ppm, 200R, 2x1.6mm; BMS_Part_Number: 9157046; Part_Type: Crystal_Osc; Part_Preference: Recommended; Manufacturer: NDK; Manufacturer_Part_Number: NX2016SA-16MHZ-EXS00A-CS07826; Component_Country_Of_Origin: Unknown; ShowFields: YES; ID: 3576
X3 = MCD-02291: Crystal, 32.768kHz, 9pF, +/-20ppm, 70KR, 1.6x1mm; Part_Type: Crystal_Osc; Part_Preference: Recommended; Manufacturer: NDK; Manufacturer_Part_Number: NX1610SE-32.768KHZ-EXS00A-MU01499; Component_Country_Of_Origin: Unknown; ShowFields: YES; ID: 4391

## Sheet STM32_microcontroller_power.SchDoc: STM32 microcontroller power
size A4; Date: Not used; ApprovedBy: Not used; CheckedBy: Not used; Author: Not used; CompanyName: STMicroelectronics; DrawnBy: Not used; Engineer: Not used; Organization: Not used; Address1: Not used; Address2: Not used; Address3: Not used; Address4: Not used; DocumentNumber: 4; Revision: Not used; SheetNumber: 4; SheetTotal: 9
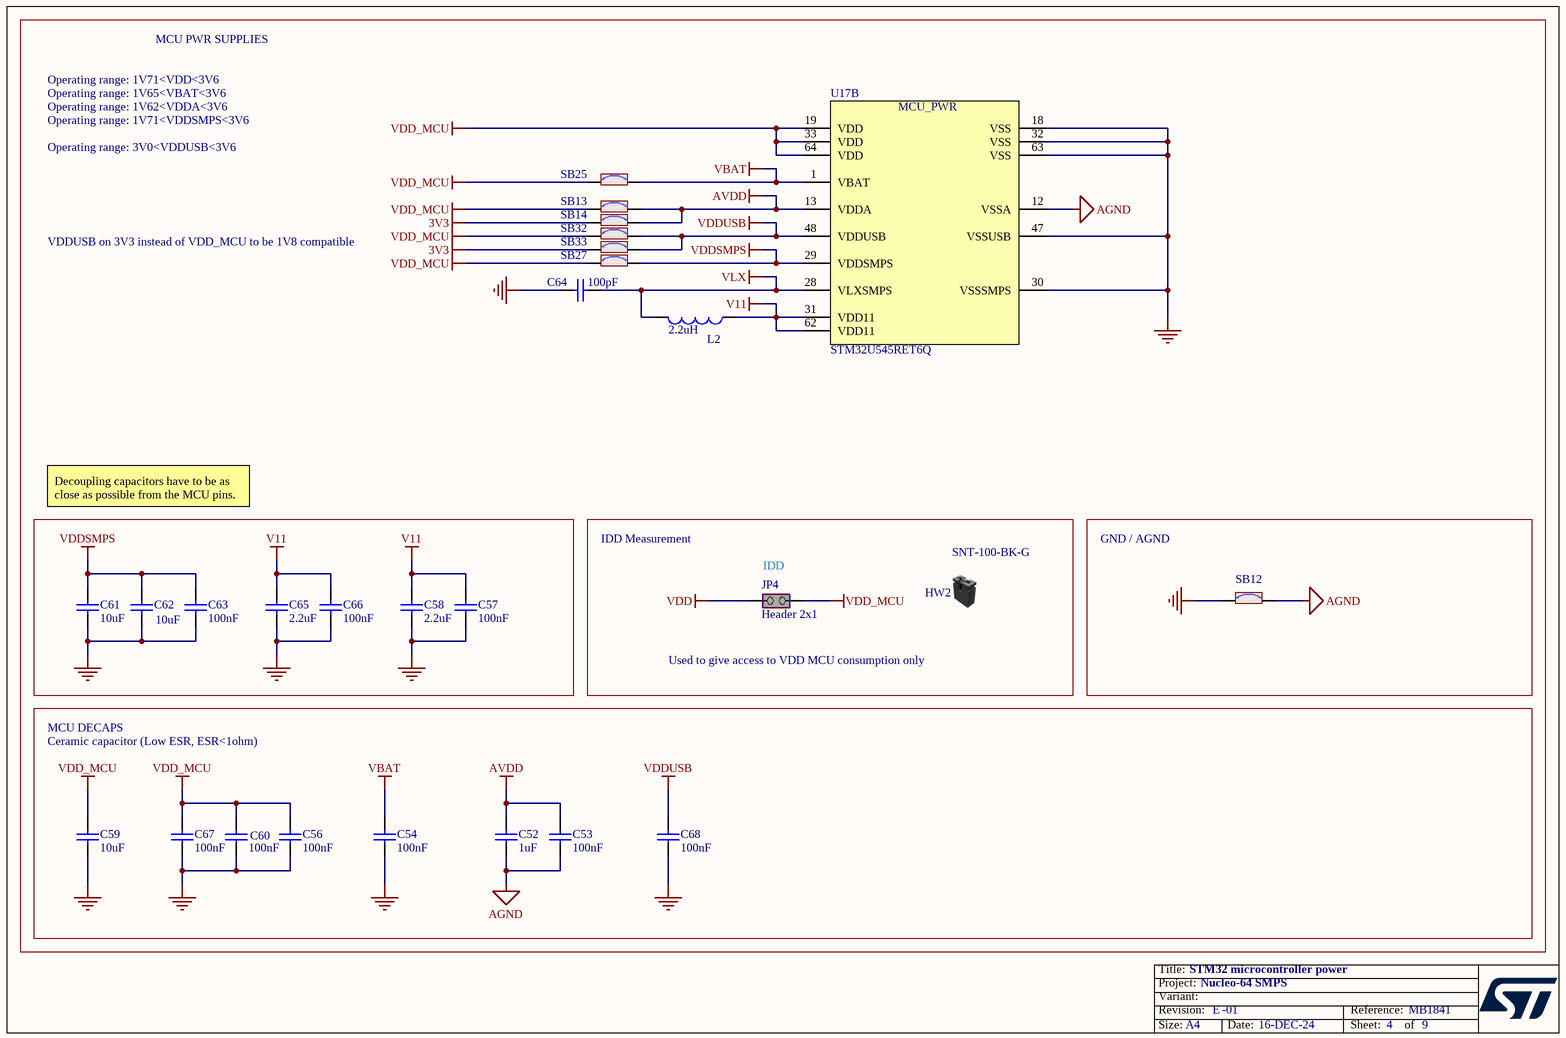
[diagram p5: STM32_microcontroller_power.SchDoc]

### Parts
C52  value 1uF  [C0603]  (hidden comment: Capacitor)
C53  value 100nF  [C0402]  (hidden comment: Capacitor)
C54  value 100nF  [C0402]  (hidden comment: Capacitor)
C56  value 100nF  [C0402]  (hidden comment: Capacitor)
C57  value 100nF  [C0402]  (hidden comment: Capacitor)
C58  value 2.2uF  [C0402]  (hidden comment: Capacitor)
C59  value 10uF  [C0402]  (hidden comment: Capacitor)
C60  value 100nF  [C0402]  (hidden comment: Capacitor)
C61  value 10uF  [C0402]  (hidden comment: Capacitor)
C62  value 10uF  [C0402]  (hidden comment: Capacitor)
C63  value 100nF  [C0402]  (hidden comment: Capacitor)
C64  value 100pF  [C0402]  (hidden comment: Capacitor)
C65  value 2.2uF  [C0402]  (hidden comment: Capacitor)
C66  value 100nF  [C0402]  (hidden comment: Capacitor)
C67  value 100nF  [C0402]  (hidden comment: Capacitor)
C68  value 100nF  [C0402]  (hidden comment: Capacitor)
HW2  value SNT-100-BK-G  (hidden comment: Shunt Black 2.54mm)  (mechanical)
JP4  value Header 2x1  [CON_SAMTEC_TSW-102-07-G-S]  (hidden comment: Jumper_Header 2x1 Fitted)
L2  value 2.2uH  [L0805_H0P9]  (hidden comment: Inductor)
SB12  SB_ON  [SOLDER-BRIDGE_R0603-0R]  (value not drawn)
SB13  SB_ON  [SOLDER-BRIDGE_R0603-0R]  (value not drawn)
SB14  SB_ON  [SOLDER-BRIDGE_R0603-0R]  (value not drawn)
SB25  SB_ON  [SOLDER-BRIDGE_R0603-0R]  (value not drawn)
SB27  SB_ON  [SOLDER-BRIDGE_R0603-0R]  (value not drawn)
SB32  SB_ON  [SOLDER-BRIDGE_R0603-0R]  (value not drawn)
SB33  SB_ON  [SOLDER-BRIDGE_R0603-0R]  (value not drawn)
U17  STM32U545RET6Q  [ICC_LQFP64_10X10_P050_SOCKET_YAMAICHI_IC149-064-069-B5_NM]  (part B of 2)

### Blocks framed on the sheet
GND / AGND: SB12

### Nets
3V3: SB14.1 SB33.1
AGND: C52.2 C53.1 SB12.2 U17.12(VSSA)
AVDD: C52.1 C53.2 SB13.2 SB14.2 U17.13(VDDA)
GND: C54.1 C56.1 C57.1 C58.1 C59.1 C60.1 C61.1 C62.1 C63.1 C64.1 C65.1 C66.1 C67.1 C68.1 SB12.1 U17.18(VSS) U17.30(VSSSMPS) U17.32(VSS) U17.47(VSSUSB) U17.63(VSS)
V11: C57.2 C58.2 C65.2 C66.2 L2.1 U17.31(VDD11) U17.62(VDD11)
VBAT: C54.2 SB25.2 U17.1(VBAT)
VDD: JP4.1(COMMON)
VDD_MCU: C56.2 C59.2 C60.2 C67.2 JP4.2(NO) SB13.1 SB25.1 SB27.1 SB32.1 U17.19(VDD) U17.33(VDD) U17.64(VDD)
VDDSMPS: C61.2 C62.2 C63.2 SB27.2 U17.29(VDDSMPS)
VDDUSB: C68.2 SB32.2 SB33.2 U17.48(VDDUSB)
VLX: C64.2 L2.2 U17.28(VLXSMPS)

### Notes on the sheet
- MCU PWR SUPPLIES
- Operating range: 1V71<VDD<3V6
- Operating range: 1V62<VDDA<3V6
- Operating range: 1V65<VBAT<3V6
- Operating range: 3V0<VDDUSB<3V6
- Operating range: 1V71<VDDSMPS<3V6
- VDDUSB on 3V3 instead of VDD_MCU to be 1V8 compatible
- Decoupling capacitors have to be as close as possible from the MCU pins.
- IDD Measurement
- (near JP4) IDD
- Used to give access to VDD MCU consumption only
- MCU DECAPS
- Ceramic capacitor (Low ESR, ESR<1ohm)

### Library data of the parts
C52 = MCD-00010: as C43 on sheet Power
C53 C54 C56 C57 C60 C63 C66-C68 = MCD-00006: as C38 on sheet Power
C58 C65 = MCD-01823: Capacitor, MLCC, 2.2uF, 6V3, X5R,+/-10%, 0402, T=0.5mm; Manufacturer_Part_Number: GRM155R60J225KE95D; Manufacturer: MURATA; Part_Preference: Recommended; Order_Code_RS: 172-6478; Component_Country_Of_Origin: Japan; ShowFields: YES; ID: 3923
C59 C61 C62 = MCD-01355: Capacitor, MLCC, 10uF, 4V, X5R, +/-20%, 0402, T=0.5mm; Manufacturer_Part_Number: GRM155R60G106ME44; Manufacturer: MURATA; Part_Preference: Recommended; Order_Code_RS: 172-6477; Component_Country_Of_Origin: Japan; ShowFields: YES; ID: 3455
C64 = MCD-00205: Capacitor, MLCC, 100pF, 50V, NPO, +/-5%, 0402, T=0.5mm; Part_Preference: Recommended; Manufacturer: YAGEO; Manufacturer_Part_Number: CC0402JRNPO9BN101; Component_Country_Of_Origin: China; ShowFields: YES; ID: 2658
HW2 = MCD-00043: as HW5 on sheet Power
JP4 = MCD-00683: Header, 2x1, 2.54mm, VR, TH, T=5.84mm/2.54mm; Part_Type: Connector; Manufacturer_Part_Number: TSW-102-07-G-S; Manufacturer: SAMTEC; Part_Preference: Recommended; Full_Alternate_Internal_Part_Number: MCD-02389; Partial_Alternate_Internal_Part_Number: MCD-02957; Order_Code_RS: 155-5312; Component_Country_Of_Origin: China, Costa Rica, Malaysia, United States, Vietnam; ShowFields: YES; ID: 3057
L2 = MCD-01060: Inductor, 2.2uH, +/-20%, 0.7A, 0R156, 0805, T=0.9mm; Part_Preference: Recommended; Manufacturer: MURATA; Manufacturer_Part_Number: LQM21PN2R2MGH; Order_Code_RS: 166-9883; Component_Country_Of_Origin: Japan; ShowFields: YES; ID: 2963
SB12-SB14 SB25 SB27 SB32 SB33 = MCD-00071: as SB9 on sheet Arduino_extension_connectors
U17 = MCD-03267: as U17 on sheet STM32_microcontroller_IOs

## Sheet USB.SchDoc: USB USER
size A4; Date: Not used; ApprovedBy: Not used; CheckedBy: Not used; Author: Not used; CompanyName: STMicroelectronics; DrawnBy: Not used; Engineer: Not used; Organization: Not used; Address1: Not used; Address2: Not used; Address3: Not used; Address4: Not used; DocumentNumber: 7; Revision: Not used; SheetNumber: 7; SheetTotal: 9
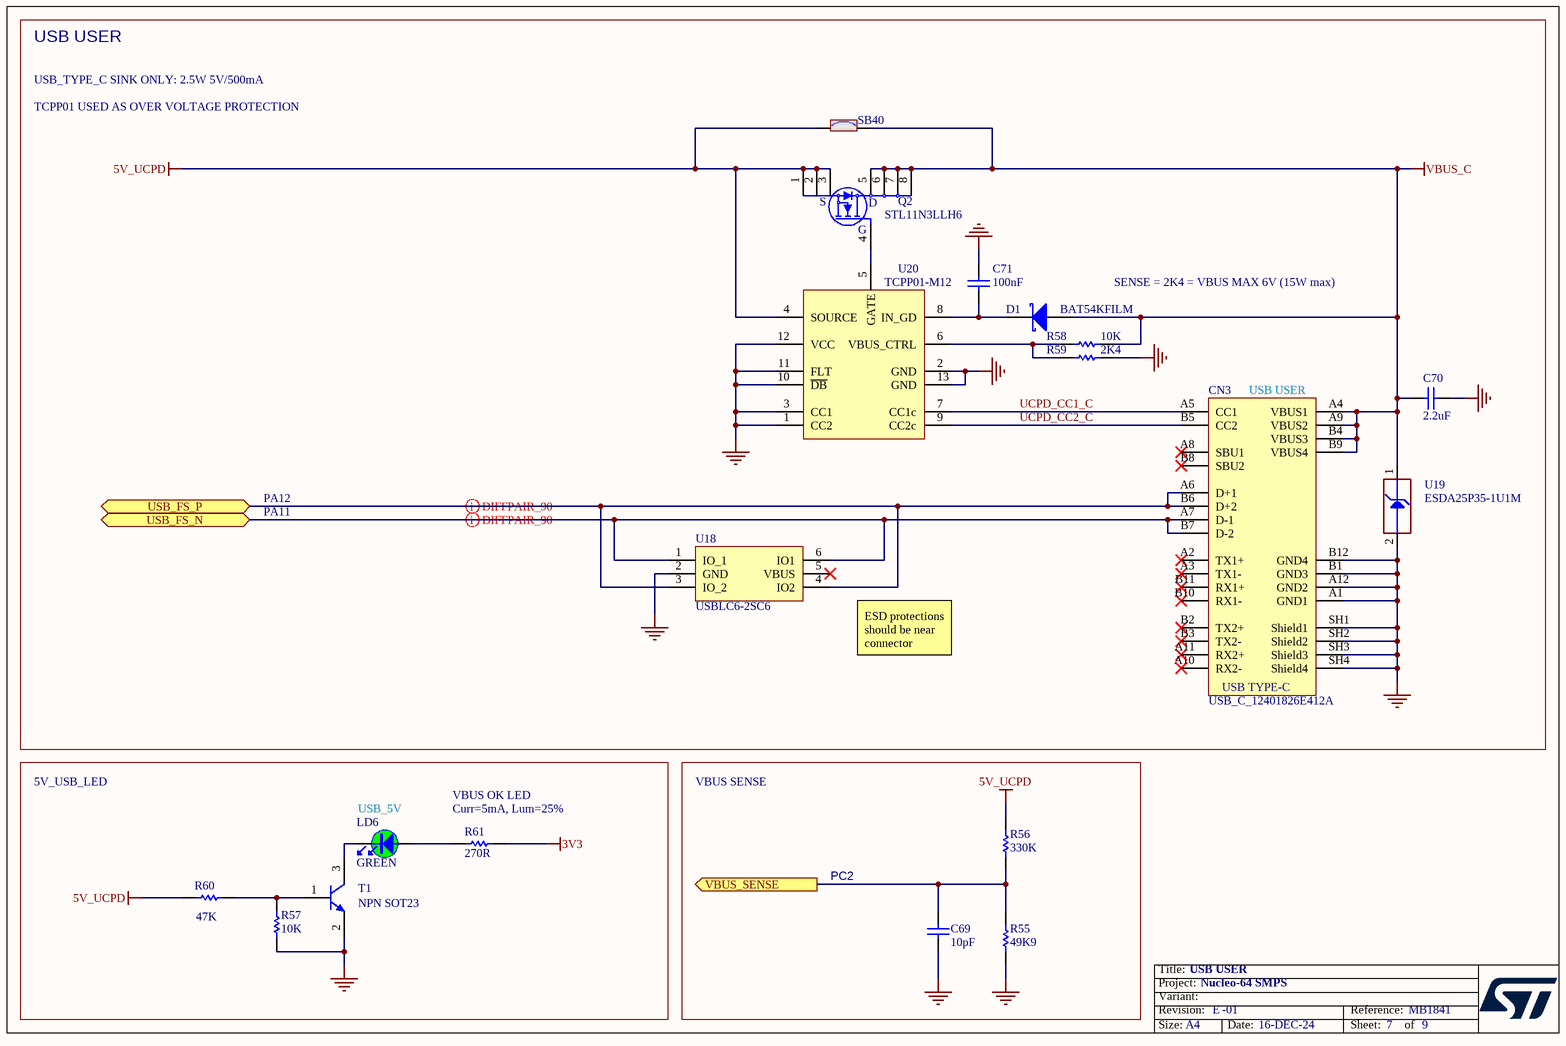
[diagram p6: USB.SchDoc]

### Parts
C69  value 10pF  [C0603]  (hidden comment: Capacitor)
C70  value 2.2uF  [C0805]  (hidden comment: Capacitor)
C71  value 100nF  [C0603]  (hidden comment: Capacitor)
CN3  value USB_C_12401826E412A  [CON_USB-TYPEC_AMPHENOL_12401826E412A]  (hidden comment: USB_TYPE_C_Receptacle)
D1  value BAT54KFILM  [DIO_SOD523_1A_2K]  (hidden comment: SCHOTTKY_1A_2K)
LD6  value GREEN  [LED_0603_OSRAM_LG-Q396-PS-35_GREEN_1A2K_H0P4]  (hidden comment: LED_green)
Q2  STL11N3LLH6  [MOS_POWERFLAT_3P3X3P3_P065]
R55  value 49K9  [R0603]  (hidden comment: Resistor)
R56  value 330K  [R0603]  (hidden comment: Resistor)
R57  value 10K  [R0402]  (hidden comment: Resistor)
R58  value 10K  [R0402]  (hidden comment: Resistor)
R59  value 2K4  [R0402]  (hidden comment: Resistor)
R60  value 47K  [R0402]  (hidden comment: Resistor)
R61  value 270R  [R0402]  (hidden comment: Resistor)
SB40  SB_ON  [SOLDER-BRIDGE_R0603-0R]  (value not drawn)
T1  value NPN SOT23  [NPN_SOT23]  (hidden comment: 9013-SOT23)
U18  USBLC6-2SC6  [ESD_SOT23-6L]
U19  value ESDA25P35-1U1M  [ESD_QFN1610_2N_1K_2A]  (hidden comment: ESD-TRANSIL)
U20  TCPP01-M12  [ICC_QFN12L-EPAD_3X3_P050]

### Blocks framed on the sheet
USB USER: C70 C71 CN3 D1 Q2 R58 R59 SB40 U18-U20

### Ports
USB_FS_N (bidir), USB_FS_P (bidir), VBUS_SENSE (out)

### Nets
3V3: R61.2
5V_UCPD: Q2.1(S) Q2.2(S) Q2.3(S) R56.2 R60.1 SB40.1 U20.4(SOURCE)
GND: C69.1 C70.1 C71.1 CN3.A1(GND1) CN3.A12(GND2) CN3.B1(GND3) CN3.B12(GND4) CN3.SH1(Shield1) CN3.SH2(Shield2) CN3.SH3(Shield3) CN3.SH4(Shield4) R55.1 R57.1 R59.2 T1.2(E) U18.2(GND) U19.2(GND) U20.1(CC2) U20.2(GND) U20.3(CC1) U20.10(~{DB}) U20.11(FLT) U20.12(VCC) U20.13(GND)
VBUS_C: C70.2 CN3.A4(VBUS1) CN3.A9(VBUS2) CN3.B4(VBUS3) CN3.B9(VBUS4) D1.1(A) Q2.5(D) Q2.6(D) Q2.7(D) Q2.8(D) R58.1 SB40.2 U19.1(IO1)
UCPD_CC1_C: CN3.A5(CC1) U20.7(CC1c)
UCPD_CC2_C: CN3.B5(CC2) U20.9(CC2c)
USB_FS_N: CN3.A7(D-1) CN3.B7(D-2) U18.1(IO_1) U18.6(IO1) ; port USB_FS_N
USB_FS_P: CN3.A6(D+1) CN3.B6(D+2) U18.3(IO_2) U18.4(IO2) ; port USB_FS_P
VBUS_SENSE: C69.2 R55.2 R56.1 ; port VBUS_SENSE
NetC71_2: C71.2 D1.2(K) U20.8(IN_GD)
NetLD6_1: LD6.1 R61.1
NetLD6_2: LD6.2 T1.3(C)
NetQ2_4: Q2.4(G) U20.5(GATE)
NetR57_2: R57.2 R60.2 T1.1(B)
NetR58_2: R58.2 R59.1 U20.6(VBUS_CTRL)

Not connected (* = marked no-connect by the designer): CN3 A2(TX1+)* A3(TX1-)* A8(SBU1)* A10(RX2-)* A11(RX2+)* B2(TX2+)* B3(TX2-)* B8(SBU2)* B10(RX1-)* B11(RX1+)*; U18 5(VBUS)*

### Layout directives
differential pair: USB_FS_N, USB_FS_P

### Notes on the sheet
- USB_TYPE_C SINK ONLY: 2.5W 5V/500mA
- TCPP01 USED AS OVER VOLTAGE PROTECTION
- SENSE = 2K4 = VBUS MAX 6V (15W max)
- (near CN3) USB USER
- PA11
- PA12
- ESD protections should be near connector
- 5V_USB_LED
- VBUS SENSE
- (near LD6) USB_5V
- (near R61) VBUS OK LED
- (near R61) Curr=5mA, Lum=25%
- PC2

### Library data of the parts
C69 = MCD-00637: Capacitor, MLCC, 10pF, 50V, NPO, +/-5%, 0603, T=0.8mm; Manufacturer_Part_Number: CC0603JRNPO9BN100; Manufacturer: YAGEO; Part_Preference: Recommended; Order_Code_RS: 616-9054; Component_Country_Of_Origin: China; ShowFields: YES; ID: 3104
C70 = MCD-02372: Capacitor, MLCC, 2.2uF, 25V, X7R, +/-10%, 0805, T=1,25mm; Part_Preference: Recommended; Manufacturer: MURATA; Manufacturer_Part_Number: GRM21BR71E225KE11L; Component_Country_Of_Origin: Japan; ShowFields: YES; ID: 4478
C71 = MCD-01099: Capacitor, MLCC, 100nF, 50V, X7R, +/-10%, 0603, T=0.8mm; Manufacturer_Part_Number: CC0603KRX7R9BB104; Manufacturer: YAGEO; BMS_Part_Number: 9142278; Part_Preference: Recommended; Order_Code_RS: 669-8767; Component_Country_Of_Origin: China; ShowFields: YES; ID: 3397
CN3 = MCD-03232: USB_TypeC, 24 pins, RA, SMD, T=2.96mm (USB Certified 3.1); Part_Type: Connector; Part_Preference: Recommended; Manufacturer: AMPHENOL ICC; Manufacturer_Part_Number: 12401826E412A; ShowFields: YES; ID: 5348
D1 = MCD-01677: Small signal Schottky diodes; Part_Type: Diode; Manufacturer: STMICROELECTRONICS; BMS_Part_Number: 9151123; Part_Preference: Recommended; Manufacturer_HQ_COO: EU; Component_Country_Of_Origin: China; ShowFields: YES; ID: 3777
LD6 = MCD-00588: as LD2 on sheet Arduino_extension_connectors
Q2 = MCD-01810: N-channel 30 V, 6 mΩ typ, 11 A STripFET™ H6, Power MOSFET in a PowerFLAT™ 3.3x3.3 package; Part_Type: IC; Manufacturer: STMICROELECTRONICS; BMS_Part_Number: 9153561; Part_Preference: Recommended; Manufacturer_HQ_COO: EU; Partial_Alternate_Internal_Part_Number: MCD-03269; Component_Country_Of_Origin: China; ShowFields: YES; ID: 3910; Alternate_EMS: A,
R55 = MCD-01171: Resistor, 49K9, 0603, +/-1%, 1/10W; Manufacturer_Part_Number: RC0603FR-0749K9L; Manufacturer: YAGEO; Part_Preference: Recommended; Component_Country_Of_Origin: China; ShowFields: YES; ID: 3324
R56 = MCD-00458: Resistor, 330K, 0603, +/-1%, 1/10W; Manufacturer_Part_Number: RC0603FR-07330KL; Manufacturer: YAGEO; Part_Preference: Recommended; Component_Country_Of_Origin: China; ShowFields: YES; ID: 2819
R57 R58 = MCD-00053: as R54 on sheet STM32_microcontroller_IOs
R59 = MCD-00433: Resistor, 2K4, 0402, +/-1%, 1/16W; Part_Preference: Recommended; Manufacturer: YAGEO; Manufacturer_Part_Number: RC0402FR-072K4L; Component_Country_Of_Origin: China; ShowFields: YES; ID: 2843
R60 = MCD-00063: as R53 on sheet Arduino_extension_connectors
R61 = MCD-00441: as R49 on sheet Arduino_extension_connectors
SB40 = MCD-00071: as SB5 on sheet Power
T1 = MCD-00073: NPN Bipolar Transistor; Manufacturer_Part_Number: BSR14; Manufacturer: ON SEMICONDUCTOR; Part_Type: IC; Part_Preference: Recommended; Component_Country_Of_Origin: Unknown; ShowFields: YES; ID: 2519
U18 = MCD-00163: Very low capacitance ESD protection; Part_Type: IC; Manufacturer: STMICROELECTRONICS; BMS_Part_Number: 9151075; Part_Preference: Recommended; Manufacturer_HQ_COO: EU; Component_Country_Of_Origin: China; ShowFields: YES; ID: 2707
U19 = MCD-01207: High power Transient voltage suppressor:25V/35A EOS and ESD transients protection.; Part_Type: Diode; Manufacturer: STMICROELECTRONICS; BMS_Part_Number: 9179045; Part_Preference: Recommended; Manufacturer_HQ_COO: EU; Component_Country_Of_Origin: China; ShowFields: YES; ID: 3289
U20 = MCD-01809: USB Type-C Port Protection for USB Power Delivery, PPS compliant; Part_Type: IC; Manufacturer: STMICROELECTRONICS; BMS_Part_Number: 9151145; Part_Preference: Recommended; Manufacturer_HQ_COO: EU; Component_Country_Of_Origin: Malaysia; ShowFields: YES; ID: 3909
